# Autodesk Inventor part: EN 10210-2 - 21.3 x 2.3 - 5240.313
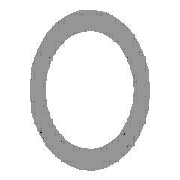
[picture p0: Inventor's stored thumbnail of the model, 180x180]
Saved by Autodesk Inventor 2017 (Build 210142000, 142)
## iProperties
Created: 2017-11
Part Number: EN 10210-2 - 21.3 x 2.3 - 5240.313
Material: Steel, Mild
Description: Pipe
Document SubType Name: Modeling
Standard: DIN
Designer: iusti
Standard Revision: 2006-07
Standards Organization: DIN
Language: en-US
Size Designation: 21.3 x 2.3
Categories: <MemberInstance><Categories><Category DisplayName="Structural Shapes" InternalName="089c4875-fa83-4c05-b084-43b9cc11f5ed" Mnemonic="GRDR"><CategoryParameter Dis
Stock Number: 21.3 x 2.3
Density: 7.85 g/cm^3
Appearance: Semi-Polished
_CCFamilyMember: 1
_CCFamilyDisplayName: DIN EN 10210-2 - Pipe
_FrameMemberDoc: Frame Member File
_Version: 15.0.0
_GetPNFromCC: 1
IsCustomPart: 1
Author: iusti
G_L: 5240.313 mm
G_W: 21.300 mm
G_H: 21.300 mm
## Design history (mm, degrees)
node "Start plane"
node "End plane"
sketch "Sketch"
  geometry: C1 r 8.35 at (0, 0); C2 r 10.65 at (0, 0); 2 further points
  constraints: 3 coincident, 2 centre point
  dimensions: "d0" = 21.3 diameter of C2 (= G_H); "d1" = 2.3 radial gap between concentric circles of C2 C1 (= G_T)
extrude "Body" new body sketch "Sketch" stored distance "d2" = 5240.31264 (= G_L); taper "d3" = 0 deg
node "Driven Length"
  sketch "Sketch3"
    geometry: L1 (0, 0)-(10, 0) reference
    constraints: 2 end point, 1 horizontal
  workplane "Work Plane3"
  sketch "Sketch4"
    geometry: L1 (-2, 0)-(12, 0) reference; L2 (-2, 5240.313)-(12, 5240.313) reference
    dimensions: "d7" = 5240.31264 distance between parallel lines of L1 L2 (derived)
body "Solid1"
other parameters: "G_H" = 21.3 [user parameter; used in 1 equation term], "G_T" = 2.3 [user parameter; used in 1 equation term], "G_L" = 5240.31264 (= d7) [user parameter; used in 1 equation term], "G_OFFSET_START" = 0 [user parameter; used in 1 equation term], "G_OFFSET_END" = 0 [user parameter; used in 1 equation term], "d4" = 0 (computed from G_OFFSET_START), "d5" = 5240.31264 (= G_OFFSET_END + B_L), "B_L" = 5240.31264 [user parameter; used in 1 equation term], "d6" = 90 deg
